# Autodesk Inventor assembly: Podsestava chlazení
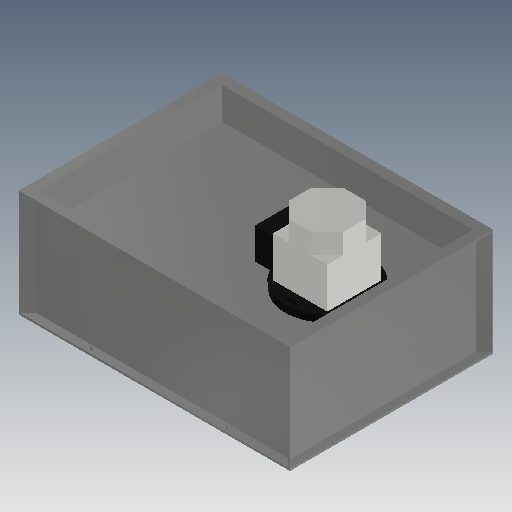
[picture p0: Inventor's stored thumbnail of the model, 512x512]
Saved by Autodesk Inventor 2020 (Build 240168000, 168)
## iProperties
Created: 2025-03
Part Number: Podsestava chlazení
Document SubType Name: Assembly
Designer: doma
Author: doma
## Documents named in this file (4)
- C:\Users\doma\Desktop\Pásovka záloha\Workgroups\NotInProject\Podsestava chlazení.iam
- C:\Users\doma\Desktop\Pásovka záloha\Workgroups\NotInProject\Nádrž.ipt
- C:\Users\doma\Desktop\Pásovka záloha\Workgroups\NotInProject\Svařenec přepážek.iam
- C:\Users\doma\Desktop\Pásovka záloha\Workgroups\NotInProject\Čerpadlo.ipt
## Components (3 placed, 3 different names)
1. Nádrž:1 — Proti sobě:1, Proti sobě:2, Proti sobě:3, Úhel:1
2. Svařenec přepážek:1 [sub-assembly] — Proti sobě:1, Proti sobě:2, Proti sobě:3, Proti sobě:4, Proti sobě:5
3. Čerpadlo:1 — Proti sobě:4, Proti sobě:5, Úhel:1
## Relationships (6: Mate 5, Angle 1)
- Proti sobě:1 [Mate]: Nádrž:1 ↔ Svařenec přepážek:1
- Proti sobě:2 [Mate]: Nádrž:1 ↔ Svařenec přepážek:1
- Proti sobě:3 [Mate]: Nádrž:1 ↔ Svařenec přepážek:1
- Proti sobě:4 [Mate]: Svařenec přepážek:1 ↔ Čerpadlo:1
- Proti sobě:5 [Mate]: Svařenec přepážek:1 ↔ Čerpadlo:1
- Úhel:1 [Angle]: Nádrž:1 ↔ Čerpadlo:1
